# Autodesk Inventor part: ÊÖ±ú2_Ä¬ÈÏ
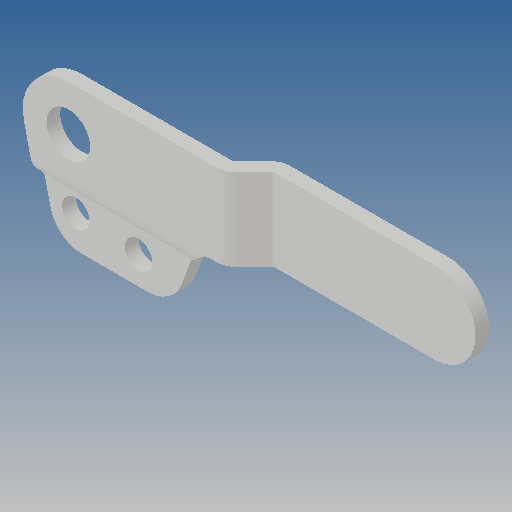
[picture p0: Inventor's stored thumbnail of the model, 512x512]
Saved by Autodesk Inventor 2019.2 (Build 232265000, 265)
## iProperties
Created: 2012-09
Part Number: ÊÖ±ú2_Ä¬ÈÏ
Material: Ogólny
Document SubType Name: Modeling
Designer: CADENGINEERING4
Density: 1 g/cm^3
Appearance: Domyślna
Author: CADENGINEERING4
Revision Number: ÈÎºÎ
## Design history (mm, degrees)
feature "NONE"
node "Bryła1"
